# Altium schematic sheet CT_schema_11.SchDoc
size 742 x 377 mm
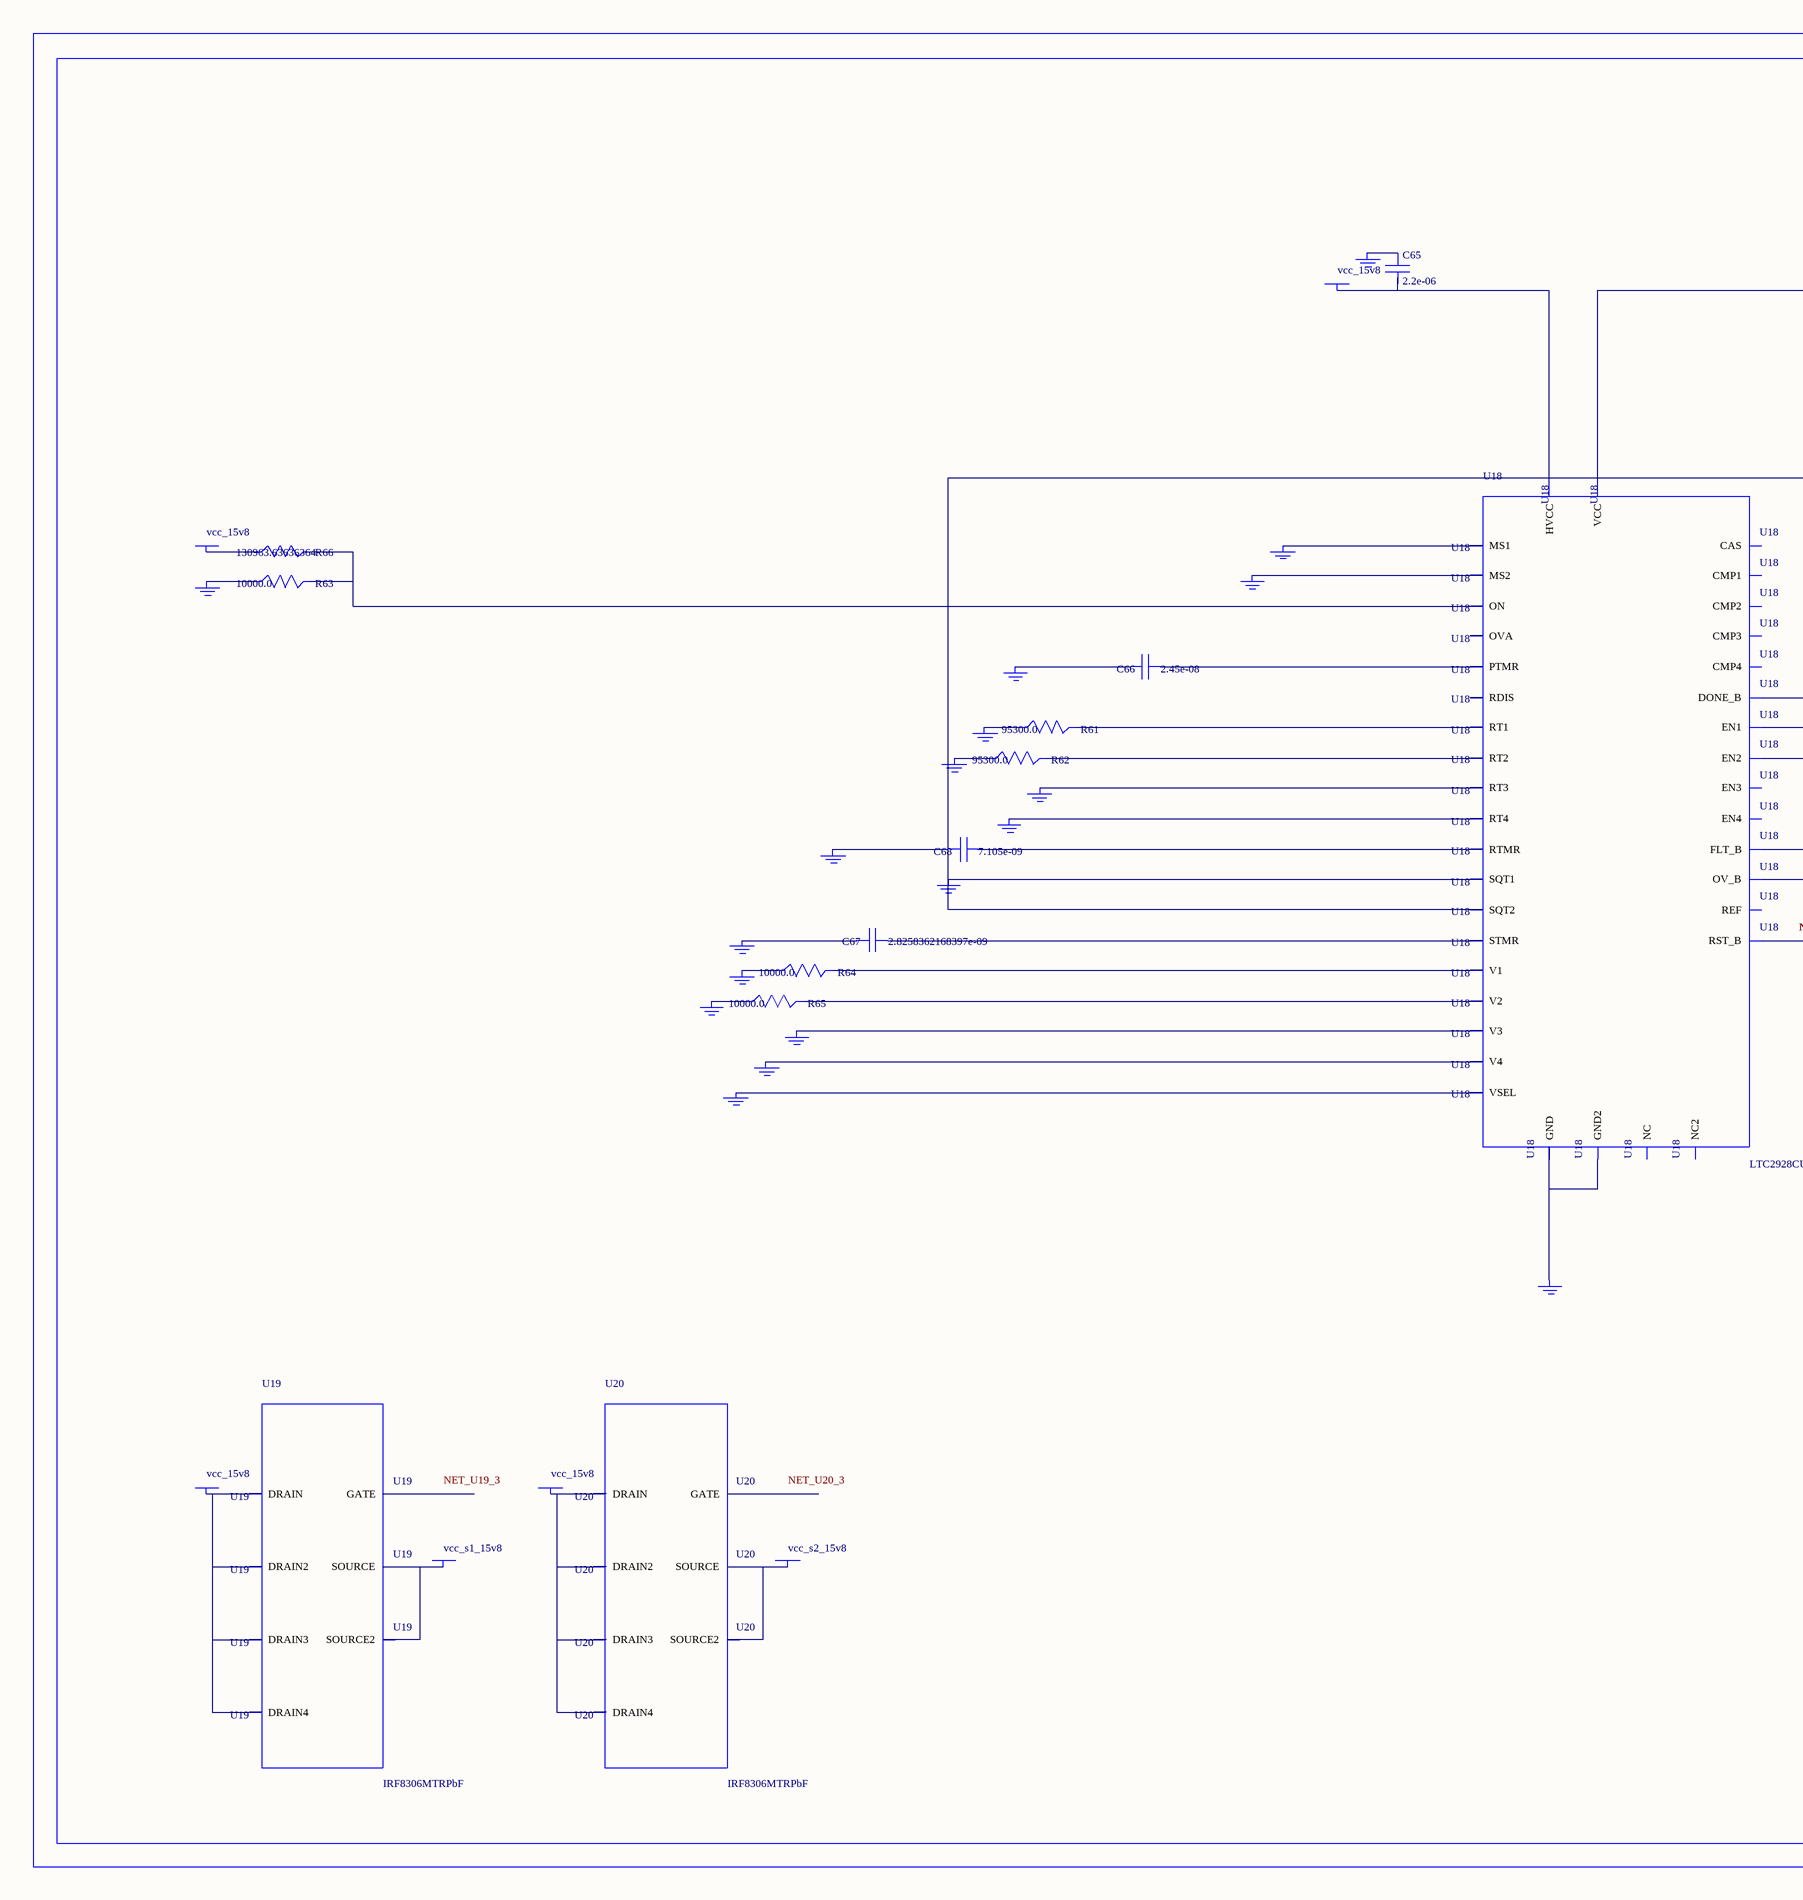
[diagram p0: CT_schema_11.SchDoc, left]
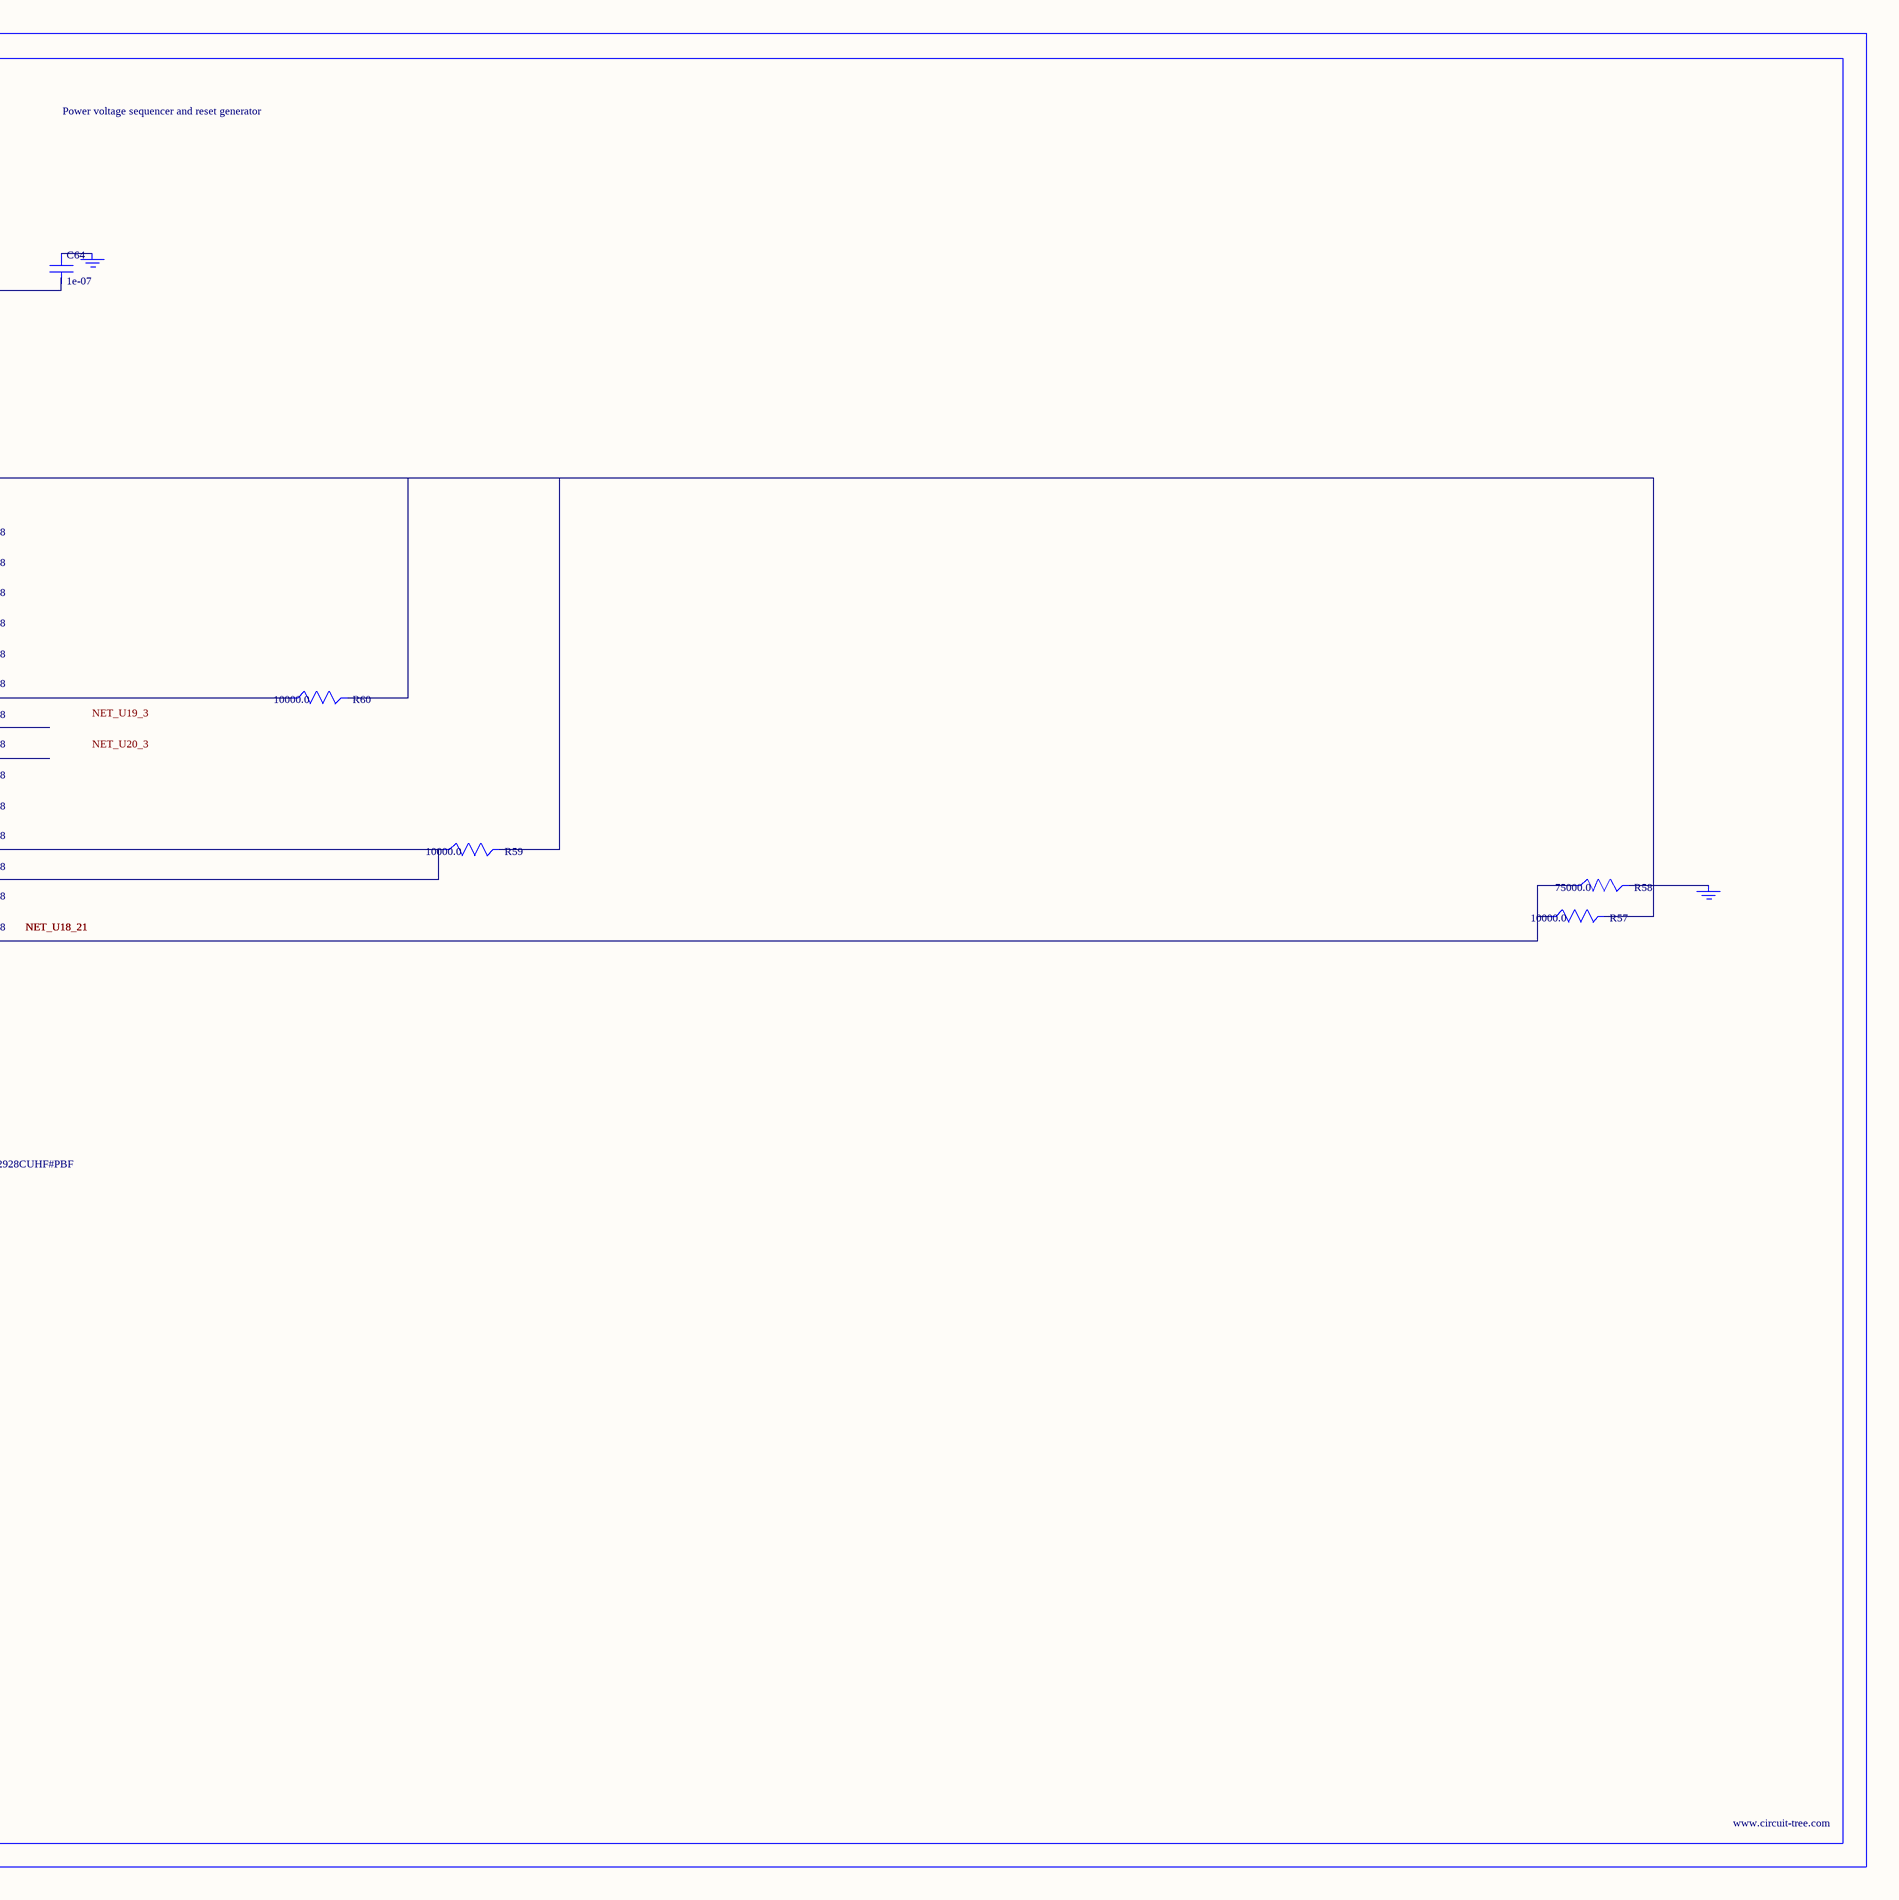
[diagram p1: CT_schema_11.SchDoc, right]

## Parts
BORDER10  (no value)
C64  1e-07  [C0402]
C65  2.2e-06  [C0603]
C66  2.45e-08  [R0603]
C67  2.8258362168397e-09  [R0603]
C68  7.105e-09  [R0603]
GND_INSTANCE_10_0  (no value)
GND_INSTANCE_10_1  (no value)
GND_INSTANCE_10_2  (no value)
GND_INSTANCE_10_3  (no value)
GND_INSTANCE_10_4  (no value)
GND_INSTANCE_10_5  (no value)
GND_INSTANCE_10_6  (no value)
GND_INSTANCE_10_7  (no value)
GND_INSTANCE_10_8  (no value)
GND_INSTANCE_10_9  (no value)
GND_INSTANCE_10_10  (no value)
GND_INSTANCE_10_11  (no value)
GND_INSTANCE_10_12  (no value)
GND_INSTANCE_10_13  (no value)
GND_INSTANCE_10_14  (no value)
GND_INSTANCE_10_15  (no value)
GND_INSTANCE_10_16  (no value)
GND_INSTANCE_10_17  (no value)
GND_INSTANCE_10_18  (no value)
GND_INSTANCE_10_19  (no value)
POWER_INSTANCE_10_0  vcc_15v8
POWER_INSTANCE_10_1  vcc_15v8
POWER_INSTANCE_10_2  vcc_15v8
POWER_INSTANCE_10_3  vcc_s1_15v8
POWER_INSTANCE_10_4  vcc_15v8
POWER_INSTANCE_10_5  vcc_s2_15v8
R57  10000.0  [R0603]
R58  75000.0  [R0603]
R59  10000.0  [R0603]
R60  10000.0  [R0603]
R61  95300.0  [R0603]
R62  95300.0  [R0603]
R63  10000.0  [R0603]
R64  10000.0  [R0603]
R65  10000.0  [R0603]
R66  130963.63636364  [R0603]
U18  LTC2928CUHF#PBF  [QFN-38_UHF]
U19  IRF8306MTRPbF  [IRF8306MTRPBF]
U20  IRF8306MTRPbF  [IRF8306MTRPBF]

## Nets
NetC64_1: C64.1 GND_INSTANCE_10_10.0(GND)
NetC64_2: C64.2 C68.2 GND_INSTANCE_10_5.0(GND) GND_INSTANCE_10_15.0(GND) R57.2 R59.2 R60.2 U18.10(SQT1) U18.11(SQT2) U18.22(VCC)
NetC65_1: C65.1 GND_INSTANCE_10_11.0(GND)
NetC65_2: C65.2 POWER_INSTANCE_10_1.0(PWR) U18.23(HVCC)
NetC66_1: C66.1 U18.27(PTMR)
NetC66_2: C66.2 GND_INSTANCE_10_14.0(GND)
NetC67_1: C67.1 U18.26(STMR)
NetC67_2: C67.2 GND_INSTANCE_10_13.0(GND)
NetC68_1: C68.1 U18.28(RTMR)
NetGND_INSTANCE_10_0_0: GND_INSTANCE_10_0.0(GND) R64.1
NetGND_INSTANCE_10_1_0: GND_INSTANCE_10_1.0(GND) R61.1
NetGND_INSTANCE_10_2_0: GND_INSTANCE_10_2.0(GND) R62.1
NetGND_INSTANCE_10_3_0: GND_INSTANCE_10_3.0(GND) U18.8(RT3)
NetGND_INSTANCE_10_4_0: GND_INSTANCE_10_4.0(GND) U18.9(RT4)
NetGND_INSTANCE_10_6_0: GND_INSTANCE_10_6.0(GND) U18.12(MS1)
NetGND_INSTANCE_10_7_0: GND_INSTANCE_10_7.0(GND) U18.13(MS2)
NetGND_INSTANCE_10_8_0: GND_INSTANCE_10_8.0(GND) R63.1
NetGND_INSTANCE_10_9_0: GND_INSTANCE_10_9.0(GND) R58.2
NetGND_INSTANCE_10_12_0: GND_INSTANCE_10_12.0(GND) U18.25(VSEL)
NetGND_INSTANCE_10_16_0: GND_INSTANCE_10_16.0(GND) U18.30(V4)
NetGND_INSTANCE_10_17_0: GND_INSTANCE_10_17.0(GND) U18.32(V3)
NetGND_INSTANCE_10_18_0: GND_INSTANCE_10_18.0(GND) R65.1
NetGND_INSTANCE_10_19_0: GND_INSTANCE_10_19.0(GND) U18.24(GND) U18.39(GND2)
NetPOWER_INSTANCE_10_0_0: POWER_INSTANCE_10_0.0(PWR) R66.1
NetPOWER_INSTANCE_10_2_0: POWER_INSTANCE_10_2.0(PWR) U19.1(DRAIN) U19.2(DRAIN2) U19.6(DRAIN3) U19.7(DRAIN4)
NetPOWER_INSTANCE_10_3_0: POWER_INSTANCE_10_3.0(PWR) U19.4(SOURCE) U19.5(SOURCE2)
NetPOWER_INSTANCE_10_4_0: POWER_INSTANCE_10_4.0(PWR) U20.1(DRAIN) U20.2(DRAIN2) U20.6(DRAIN3) U20.7(DRAIN4)
NetPOWER_INSTANCE_10_5_0: POWER_INSTANCE_10_5.0(PWR) U20.4(SOURCE) U20.5(SOURCE2)
NetR57_1: R57.1 R58.1 U18.21(RST_B)
NetR59_1: R59.1 U18.19(FLT_B) U18.20(OV_B)
NetR60_1: R60.1 U18.18(DONE_B)
NetR61_2: R61.2 U18.6(RT1)
NetR62_2: R62.2 U18.7(RT2)
NetR63_2: R63.2 R66.2 U18.16(ON)
NetR64_2: R64.2 U18.3(V1)
NetR65_2: R65.2 U18.38(V2)

Not connected (* = marked no-connect by the designer): U18 1(OVA) 2(EN1) 4(NC) 5(REF) 14(RDIS) 15(CAS) 17(NC2) 29(EN4) 31(EN3) 33(CMP3) 34(CMP4) 35(CMP1) 36(CMP2) 37(EN2); U19 3(GATE); U20 3(GATE)

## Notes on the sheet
- Labels drawn without touching a wire or pin: NET_U19_3, NET_U20_3

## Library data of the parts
BORDER10 = BORDER_PAGE10
C64 = C0402C104K3RACTU
C65 = GRM188R61H225KE1115D
C66 = C66
C67 = C67
C68 = C68
GND_INSTANCE_10_0-GND_INSTANCE_10_19 = GND
POWER_INSTANCE_10_0-POWER_INSTANCE_10_5 = PWR
R57 R59 R60 R63-R65 = RC0603JR-0710KL
R58 = RC0603JR-0775KL
R61 R62 = RC0603FR-0795K3L
R66 = R66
